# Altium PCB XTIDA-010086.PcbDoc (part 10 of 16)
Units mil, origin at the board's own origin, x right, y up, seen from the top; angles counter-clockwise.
Board outline 14763.78 x 8267.72 mil, 6 copper layers (Top Layer, GND Layer, Signal Layer 1, Signal Layer 2, Power Layer, Bottom Layer), stack 62 mil thick; 1933 components, 1002 nets, 4886 pads, 6482 vias.
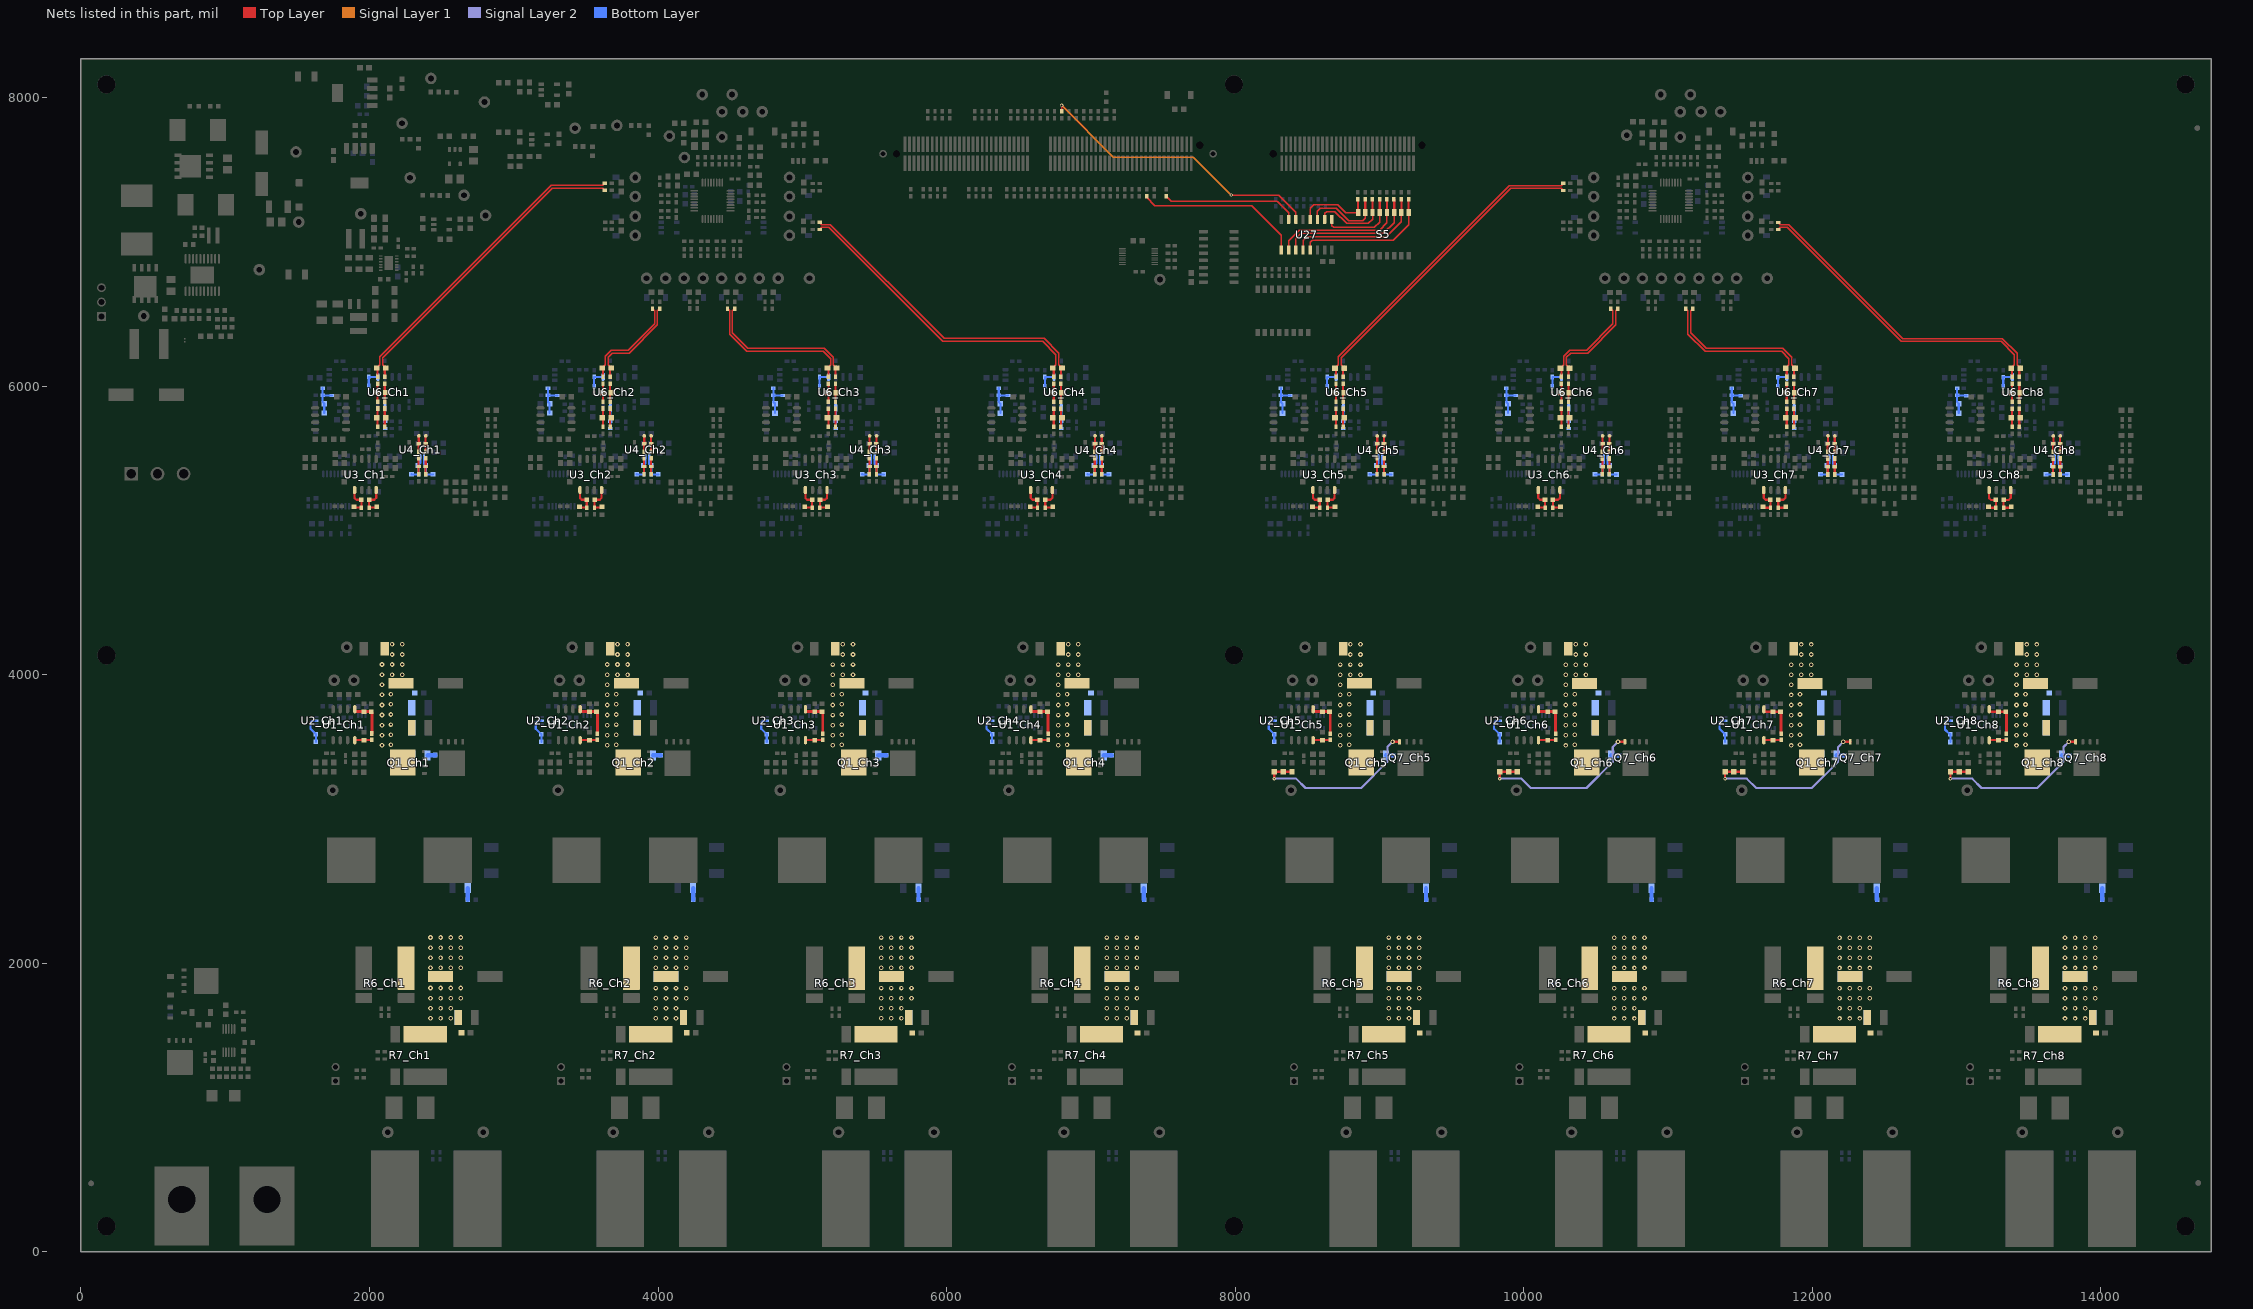
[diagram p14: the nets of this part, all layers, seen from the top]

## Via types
v1: diameter 32, hole 16, Top Layer to Bottom Layer, tented both sides, 4685 vias
v2: diameter 24, hole 12, Top Layer to Bottom Layer, tented both sides, 1013 vias
v3: diameter 32, hole 16, Top Layer to Bottom Layer, 728 vias
v4: diameter 19.68, hole 7.87, Top Layer to Bottom Layer, 40 vias
v5: diameter 214.57, hole 140, Top Layer to Bottom Layer, 16 vias

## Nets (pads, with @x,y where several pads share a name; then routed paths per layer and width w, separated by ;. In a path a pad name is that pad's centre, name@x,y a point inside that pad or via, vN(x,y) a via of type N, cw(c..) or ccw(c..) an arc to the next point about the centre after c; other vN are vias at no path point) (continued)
LDrive_Ch5: Q7_Ch5.4 R21_Ch5.1 R24_Ch5.2 R25_Ch5.2 | length 1257.7
  Top Layer w15: v2(8271.06,3279.33) R24_Ch5.2@8271.06,3327.28 R25_Ch5.2@8332.53,3327.28 R21_Ch5.1@8394.06,3327.28 ; v1(9090.75,3534.76) Q7_Ch5.4@9138.7,3534.76
  Signal Layer 2 w15: v2(8271.06,3279.33) 8422.06,3279.33 8486.7,3214.69 8872.7,3214.69 9054.7,3396.69 9054.7,3498.72 v1(9090.75,3534.76)
LDrive_Ch6: Q7_Ch6.4 R21_Ch6.1 R24_Ch6.2 R25_Ch6.2 | length 1257.7
  Top Layer w15: v2(9833.06,3279.25) R24_Ch6.2@9833.06,3327.2 R25_Ch6.2@9894.53,3327.2 R21_Ch6.1@9956.06,3327.2 ; v1(10652.75,3534.69) Q7_Ch6.4@10700.7,3534.69
  Signal Layer 2 w15: v2(9833.06,3279.25) 9984.06,3279.25 10048.7,3214.61 10434.7,3214.61 10616.7,3396.61 10616.7,3498.64 v1(10652.75,3534.69)
LDrive_Ch7: Q7_Ch7.4 R21_Ch7.1 R24_Ch7.2 R25_Ch7.2 | length 1257.7
  Top Layer w15: v2(11395.06,3279.17) R24_Ch7.2@11395.06,3327.12 R25_Ch7.2@11456.53,3327.12 R21_Ch7.1@11518.06,3327.12 ; v1(12214.75,3534.61) Q7_Ch7.4@12262.7,3534.61
  Signal Layer 2 w15: v2(11395.06,3279.17) 11546.06,3279.17 11610.7,3214.53 11996.7,3214.53 12178.7,3396.53 12178.7,3498.56 v1(12214.75,3534.61)
LDrive_Ch8: Q7_Ch8.4 R21_Ch8.1 R24_Ch8.2 R25_Ch8.2 | length 1257.7
  Top Layer w15: v2(12957.06,3279.09) R24_Ch8.2@12957.06,3327.05 R25_Ch8.2@13018.53,3327.05 R21_Ch8.1@13080.06,3327.05 ; v1(13776.75,3534.53) Q7_Ch8.4@13824.7,3534.53
  Signal Layer 2 w15: v2(12957.06,3279.09) 13108.06,3279.09 13172.7,3214.45 13558.7,3214.45 13740.7,3396.45 13740.7,3498.48 v1(13776.75,3534.53)
LTV_-2.5V_Ch1: C55_Ch1.2 R76_Ch1.1 R78_Ch1.2 R79_Ch1.2 R219_Ch1.2 | length 240.8
  Bottom Layer w15: R219_Ch1.2@1675.38,5985 1675.62,5984.76 R79_Ch1.2@1675.62,5935.7 ; R78_Ch1.2@1686.71,5813.03 C55_Ch1.2@1686.71,5878.7 1675.62,5889.79 R79_Ch1.2@1675.62,5935.7 ; R76_Ch1.1@1739.38,5934.7 1738.38,5935.7 R79_Ch1.2@1675.62,5935.7
LTV_-2.5V_Ch2: C55_Ch2.2 R76_Ch2.1 R78_Ch2.2 R79_Ch2.2 R219_Ch2.2 | length 240.5
  Bottom Layer w15: R219_Ch2.2@3237.62,5984.68 R79_Ch2.2@3237.62,5935.62 ; R78_Ch2.2@3248.71,5812.95 C55_Ch2.2@3248.71,5878.62 3237.62,5889.71 R79_Ch2.2@3237.62,5935.62 ; R76_Ch2.1@3301.38,5934.62 3300.38,5935.62 R79_Ch2.2@3237.62,5935.62
LTV_-2.5V_Ch3: C55_Ch3.2 R76_Ch3.1 R78_Ch3.2 R79_Ch3.2 R219_Ch3.2 | length 240.5
  Bottom Layer w15: R219_Ch3.2@4799.62,5984.6 R79_Ch3.2@4799.62,5935.54 ; R78_Ch3.2@4810.71,5812.87 C55_Ch3.2@4810.71,5878.54 4799.62,5889.63 R79_Ch3.2@4799.62,5935.54 ; R76_Ch3.1@4863.38,5934.54 4862.38,5935.54 R79_Ch3.2@4799.62,5935.54
LTV_-2.5V_Ch4: C55_Ch4.2 R76_Ch4.1 R78_Ch4.2 R79_Ch4.2 R219_Ch4.2 | length 240.5
  Bottom Layer w15: R219_Ch4.2@6361.62,5984.52 R79_Ch4.2@6361.62,5935.46 ; R78_Ch4.2@6372.71,5812.79 C55_Ch4.2@6372.71,5878.46 6361.62,5889.55 R79_Ch4.2@6361.62,5935.46 ; R76_Ch4.1@6425.38,5934.46 6424.38,5935.46 R79_Ch4.2@6361.62,5935.46
LTV_-2.5V_Ch5: C55_Ch5.2 R76_Ch5.1 R78_Ch5.2 R79_Ch5.2 R219_Ch5.2 | length 240.5
  Bottom Layer w15: R219_Ch5.2@8317.32,5984.44 R79_Ch5.2@8317.32,5935.39 ; R78_Ch5.2@8328.41,5812.71 C55_Ch5.2@8328.41,5878.39 8317.32,5889.47 R79_Ch5.2@8317.32,5935.39 ; R76_Ch5.1@8381.08,5934.39 8380.08,5935.39 R79_Ch5.2@8317.32,5935.39
LTV_-2.5V_Ch6: C55_Ch6.2 R76_Ch6.1 R78_Ch6.2 R79_Ch6.2 R219_Ch6.2 | length 240.5
  Bottom Layer w15: R219_Ch6.2@9879.32,5984.36 R79_Ch6.2@9879.32,5935.31 ; R78_Ch6.2@9890.41,5812.63 C55_Ch6.2@9890.41,5878.31 9879.32,5889.39 R79_Ch6.2@9879.32,5935.31 ; R76_Ch6.1@9943.08,5934.31 9942.08,5935.31 R79_Ch6.2@9879.32,5935.31
LTV_-2.5V_Ch7: C55_Ch7.2 R76_Ch7.1 R78_Ch7.2 R79_Ch7.2 R219_Ch7.2 | length 240.5
  Bottom Layer w15: R219_Ch7.2@11441.32,5984.28 R79_Ch7.2@11441.32,5935.23 ; R78_Ch7.2@11452.41,5812.55 C55_Ch7.2@11452.41,5878.23 11441.32,5889.32 R79_Ch7.2@11441.32,5935.23 ; R76_Ch7.1@11505.08,5934.23 11504.08,5935.23 R79_Ch7.2@11441.32,5935.23
LTV_-2.5V_Ch8: C55_Ch8.2 R76_Ch8.1 R78_Ch8.2 R79_Ch8.2 R219_Ch8.2 | length 240.5
  Bottom Layer w15: R219_Ch8.2@13003.32,5984.2 R79_Ch8.2@13003.32,5935.15 ; R78_Ch8.2@13014.41,5812.48 C55_Ch8.2@13014.41,5878.15 13003.32,5889.24 R79_Ch8.2@13003.32,5935.15 ; R76_Ch8.1@13067.08,5934.15 13066.08,5935.15 R79_Ch8.2@13003.32,5935.15
MODE_A: R297.1 U27.9 | length 1152.3
  Top Layer w10: R297.1@7388,7316.38 7388,7307 7444,7251 8114,7251 8320.2,7044.8 U27.9@8320.2,6942.67
MODE_B: R296.1 U27.7 | length 943.1
  Top Layer w10: R296.1@7521,7316.38 7557.38,7280 8291.78,7280 8370.2,7201.58 U27.7@8370.2,7155.27
MODE_C: R274.1 U27.6 | length 2021.4
  Top Layer w10: R274.1@6797,7903.54 v2(6797,7945) ; v2(7972,7324) 8302,7324 8420.2,7205.8 U27.6@8420.2,7155.27
  Signal Layer 1 w10: v2(6797,7945) 7156,7586 7710,7586 v2(7972,7324)
MODE_CH1: R234.2 S5.4 U27.10 | length 962.7
  Top Layer w10: U27.10@8369.78,6942.25 U27.10@8370.2,6942.67 8370.2,7007.97 8442.78,7080.54 9001.78,7080.54 9051.86,7130.62 S5.4@9051.86,7202.54
  Top Layer w15: S5.4@9051.86,7202.54 R234.2@9051.86,7294.92
MODE_CH2: R233.2 S5.3 U27.11 | length 970.3
  Top Layer w10: U27.11@8420.2,6942.67 8419.78,6942.25 8419.78,7021.54 8456.2,7057.97 9027.2,7057.97 9101.86,7132.62 S5.3@9101.86,7202.54
  Top Layer w15: S5.3@9101.86,7202.54 R233.2@9101.86,7294.92
MODE_CH3: R232.2 S5.2 U27.12 | length 959
  Top Layer w10: U27.12@8471.08,6941.79 U27.12@8470.2,6942.67 8470.2,7008.97 8496.2,7034.97 9047.2,7034.97 9151.86,7139.62 S5.2@9151.86,7202.54
  Top Layer w15: R232.2@9150.86,7294.92 9151.86,7293.92 S5.2@9151.86,7202.54
MODE_CH4: R231.2 S5.1 U27.13 | length 964.4
  Top Layer w10: U27.13@8520.2,6942.67 8519.78,6942.25 8519.78,6996.54 8535.2,7011.97 9096.2,7011.97 9201.86,7117.62 S5.1@9201.86,7202.54
  Top Layer w15: S5.1@9201.86,7202.54 R231.2@9201.86,7294.92
MODE_CH5: R235.2 S5.5 U27.1 | length 554.8
  Top Layer w10: U27.1@8670.2,7155.27 8670.2,7110.97 8682.2,7098.97 8964.2,7098.97 9001.86,7136.62 S5.5@9001.86,7202.54
  Top Layer w15: S5.5@9001.86,7202.54 R235.2@9001.86,7294.92
MODE_CH6: R236.2 S5.6 U27.2 | length 560.9
  Top Layer w10: U27.2@8620.2,7155.27 8620.2,7195.97 8633.2,7208.97 8691.2,7208.97 8772.2,7127.97 8922.2,7127.97 8951.86,7157.62 S5.6@8951.86,7202.54
  Top Layer w15: S5.6@8951.86,7202.54 R236.2@8951.86,7294.92
MODE_CH7: R237.2 S5.7 U27.3 | length 570.5
  Top Layer w10: U27.3@8570.2,7155.27 8570.2,7212.97 8588.2,7230.97 8701.2,7230.97 8786.2,7145.97 8883.99,7145.97 8901.86,7163.84 S5.7@8901.86,7202.54
  Top Layer w15: S5.7@8901.86,7202.54 R237.2@8901.86,7294.92
MODE_CH8: R238.2 S5.8 U27.4 | length 532.8
  Top Layer w10: U27.4@8520.2,7155.27 8520.2,7231.97 8544.2,7255.97 8712.2,7255.97 8765.63,7202.54 S5.8@8851.86,7202.54
  Top Layer w15: S5.8@8851.86,7202.54 R238.2@8851.86,7294.92
NetC1_Ch1_1: C1_Ch1.1 D1_Ch1.1 U1_Ch1.8 | length 120.2
  Top Layer w15: U1_Ch1.8@1898.37,3545.79 1899.33,3546.75 C1_Ch1.1@1962.33,3546.75 2015.49,3546.75 D1_Ch1.1@2017.39,3548.65
NetC1_Ch2_1: C1_Ch2.1 D1_Ch2.1 U1_Ch2.8 | length 120.2
  Top Layer w15: U1_Ch2.8@3460.37,3545.71 3461.33,3546.67 C1_Ch2.1@3524.33,3546.67 3577.49,3546.67 D1_Ch2.1@3579.39,3548.58
NetC1_Ch3_1: C1_Ch3.1 D1_Ch3.1 U1_Ch3.8 | length 120.2
  Top Layer w15: U1_Ch3.8@5022.37,3545.63 5023.33,3546.59 C1_Ch3.1@5086.33,3546.59 5139.49,3546.59 D1_Ch3.1@5141.39,3548.5
NetC1_Ch4_1: C1_Ch4.1 D1_Ch4.1 U1_Ch4.8 | length 120.2
  Top Layer w15: U1_Ch4.8@6584.37,3545.55 6585.33,3546.51 C1_Ch4.1@6648.33,3546.51 6701.49,3546.51 D1_Ch4.1@6703.39,3548.42
NetC1_Ch5_1: C1_Ch5.1 D1_Ch5.1 U1_Ch5.8 | length 120.2
  Top Layer w15: U1_Ch5.8@8540.07,3545.47 8541.03,3546.43 C1_Ch5.1@8604.03,3546.43 8657.19,3546.43 D1_Ch5.1@8659.09,3548.34
NetC1_Ch6_1: C1_Ch6.1 D1_Ch6.1 U1_Ch6.8 | length 120.2
  Top Layer w15: U1_Ch6.8@10102.07,3545.39 10103.03,3546.35 C1_Ch6.1@10166.03,3546.35 10219.19,3546.35 D1_Ch6.1@10221.09,3548.26
NetC1_Ch7_1: C1_Ch7.1 D1_Ch7.1 U1_Ch7.8 | length 120.2
  Top Layer w15: U1_Ch7.8@11664.07,3545.31 11665.03,3546.28 C1_Ch7.1@11728.03,3546.28 11781.19,3546.28 D1_Ch7.1@11783.09,3548.18
NetC1_Ch8_1: C1_Ch8.1 D1_Ch8.1 U1_Ch8.8 | length 120.2
  Top Layer w15: U1_Ch8.8@13226.07,3545.23 13227.03,3546.2 C1_Ch8.1@13290.03,3546.2 13343.19,3546.2 D1_Ch8.1@13345.09,3548.1
NetC2_Ch1_2: C2_Ch1.2 R4_Ch1.2 | length 54.7
  Bottom Layer w30: R4_Ch1.2@2403.15,3441 2456.44,3441 C2_Ch1.2@2457.44,3442
NetC2_Ch2_2: C2_Ch2.2 R4_Ch2.2 | length 54.7
  Bottom Layer w30: R4_Ch2.2@3965.15,3440.92 4018.44,3440.92 C2_Ch2.2@4019.44,3441.92
NetC2_Ch3_2: C2_Ch3.2 R4_Ch3.2 | length 54.7
  Bottom Layer w30: R4_Ch3.2@5527.15,3440.84 5580.44,3440.84 C2_Ch3.2@5581.44,3441.84
NetC2_Ch4_2: C2_Ch4.2 R4_Ch4.2 | length 54.7
  Bottom Layer w30: R4_Ch4.2@7089.15,3440.76 7142.44,3440.76 C2_Ch4.2@7143.44,3441.76
NetC2_Ch5_2: C2_Ch5.2 R4_Ch5.2 | length 54.7
  Bottom Layer w30: R4_Ch5.2@9044.85,3440.69 9098.14,3440.69 C2_Ch5.2@9099.14,3441.69
NetC2_Ch6_2: C2_Ch6.2 R4_Ch6.2 | length 54.7
  Bottom Layer w30: R4_Ch6.2@10606.85,3440.61 10660.14,3440.61 C2_Ch6.2@10661.14,3441.61
NetC2_Ch7_2: C2_Ch7.2 R4_Ch7.2 | length 54.7
  Bottom Layer w30: R4_Ch7.2@12168.85,3440.53 12222.14,3440.53 C2_Ch7.2@12223.14,3441.53
NetC2_Ch8_2: C2_Ch8.2 R4_Ch8.2 | length 54.7
  Bottom Layer w30: R4_Ch8.2@13730.85,3440.45 13784.14,3440.45 C2_Ch8.2@13785.14,3441.45
NetC3_Ch1_1: C3_Ch1.1 C4_Ch1.1 C5_Ch1.1 C6_Ch1.1 C7_Ch1.1 L1_Ch1.2 Q1_Ch1.5 Q1_Ch1.6 Q1_Ch1.7 Q1_Ch1.8 Q1_Ch1.9@2231.39,3391 R4_Ch1.1
  other v1: 2087,3510 2149,3514 2087,3580 2149,3584 2087,3650 2149,3654 2087,3720 2149,3724 2087,3790 2149,3794 2087,3860 2149,3864 2087,3930 2087,4000 2157,4000 2227,4000 2087,4070 2157,4070 2227,4070 2157,4140 2227,4140 2157,4210 2227,4210
NetC3_Ch2_1: C3_Ch2.1 C4_Ch2.1 C5_Ch2.1 C6_Ch2.1 C7_Ch2.1 L1_Ch2.2 Q1_Ch2.5 Q1_Ch2.6 Q1_Ch2.7 Q1_Ch2.8 Q1_Ch2.9@3793.39,3390.92 R4_Ch2.1
  other v1: 3649,3509.92 3711,3513.92 3649,3579.92 3711,3583.92 3649,3649.92 3711,3653.92 3649,3719.92 3711,3723.92 3649,3789.92 3711,3793.92 3649,3859.92 3711,3863.92 3649,3929.92 3649,3999.92 3719,3999.92 3789,3999.92 3649,4069.92 3719,4069.92 3789,4069.92 3719,4139.92 3789,4139.92 3719,4209.92 3789,4209.92
NetC3_Ch3_1: C3_Ch3.1 C4_Ch3.1 C5_Ch3.1 C6_Ch3.1 C7_Ch3.1 L1_Ch3.2 Q1_Ch3.5 Q1_Ch3.6 Q1_Ch3.7 Q1_Ch3.8 Q1_Ch3.9@5355.39,3390.84 R4_Ch3.1
  other v1: 5211,3509.84 5273,3513.84 5211,3579.84 5273,3583.84 5211,3649.84 5273,3653.84 5211,3719.84 5273,3723.84 5211,3789.84 5273,3793.84 5211,3859.84 5273,3863.84 5211,3929.84 5211,3999.84 5281,3999.84 5351,3999.84 5211,4069.84 5281,4069.84 5351,4069.84 5281,4139.84 5351,4139.84 5281,4209.84 5351,4209.84
NetC3_Ch4_1: C3_Ch4.1 C4_Ch4.1 C5_Ch4.1 C6_Ch4.1 C7_Ch4.1 L1_Ch4.2 Q1_Ch4.5 Q1_Ch4.6 Q1_Ch4.7 Q1_Ch4.8 Q1_Ch4.9@6917.39,3390.76 R4_Ch4.1
  other v1: 6773,3509.76 6835,3513.76 6773,3579.76 6835,3583.76 6773,3649.76 6835,3653.76 6773,3719.76 6835,3723.76 6773,3789.76 6835,3793.76 6773,3859.76 6835,3863.76 6773,3929.76 6773,3999.76 6843,3999.76 6913,3999.76 6773,4069.76 6843,4069.76 6913,4069.76 6843,4139.76 6913,4139.76 6843,4209.76 6913,4209.76
NetC3_Ch5_1: C3_Ch5.1 C4_Ch5.1 C5_Ch5.1 C6_Ch5.1 C7_Ch5.1 L1_Ch5.2 Q1_Ch5.5 Q1_Ch5.6 Q1_Ch5.7 Q1_Ch5.8 Q1_Ch5.9@8873.09,3390.69 R4_Ch5.1
  other v1: 8728.7,3509.69 8790.7,3513.69 8728.7,3579.69 8790.7,3583.69 8728.7,3649.69 8790.7,3653.69 8728.7,3719.69 8790.7,3723.69 8728.7,3789.69 8790.7,3793.69 8728.7,3859.69 8790.7,3863.69 8728.7,3929.69 8728.7,3999.69 8798.7,3999.69 8868.7,3999.69 8728.7,4069.69 8798.7,4069.69 8868.7,4069.69 8798.7,4139.69 8868.7,4139.69 8798.7,4209.69 8868.7,4209.69
NetC3_Ch6_1: C3_Ch6.1 C4_Ch6.1 C5_Ch6.1 C6_Ch6.1 C7_Ch6.1 L1_Ch6.2 Q1_Ch6.5 Q1_Ch6.6 Q1_Ch6.7 Q1_Ch6.8 Q1_Ch6.9@10435.09,3390.61 R4_Ch6.1
  other v1: 10290.7,3509.61 10352.7,3513.61 10290.7,3579.61 10352.7,3583.61 10290.7,3649.61 10352.7,3653.61 10290.7,3719.61 10352.7,3723.61 10290.7,3789.61 10352.7,3793.61 10290.7,3859.61 10352.7,3863.61 10290.7,3929.61 10290.7,3999.61 10360.7,3999.61 10430.7,3999.61 10290.7,4069.61 10360.7,4069.61 10430.7,4069.61 10360.7,4139.61 10430.7,4139.61 10360.7,4209.61 10430.7,4209.61
NetC3_Ch7_1: C3_Ch7.1 C4_Ch7.1 C5_Ch7.1 C6_Ch7.1 C7_Ch7.1 L1_Ch7.2 Q1_Ch7.5 Q1_Ch7.6 Q1_Ch7.7 Q1_Ch7.8 Q1_Ch7.9@11997.09,3390.53 R4_Ch7.1
  other v1: 11852.7,3509.53 11914.7,3513.53 11852.7,3579.53 11914.7,3583.53 11852.7,3649.53 11914.7,3653.53 11852.7,3719.53 11914.7,3723.53 11852.7,3789.53 11914.7,3793.53 11852.7,3859.53 11914.7,3863.53 11852.7,3929.53 11852.7,3999.53 11922.7,3999.53 11992.7,3999.53 11852.7,4069.53 11922.7,4069.53 11992.7,4069.53 11922.7,4139.53 11992.7,4139.53 11922.7,4209.53 11992.7,4209.53
NetC3_Ch8_1: C3_Ch8.1 C4_Ch8.1 C5_Ch8.1 C6_Ch8.1 C7_Ch8.1 L1_Ch8.2 Q1_Ch8.5 Q1_Ch8.6 Q1_Ch8.7 Q1_Ch8.8 Q1_Ch8.9@13559.09,3390.45 R4_Ch8.1
  other v1: 13414.7,3509.45 13476.7,3513.45 13414.7,3579.45 13476.7,3583.45 13414.7,3649.45 13476.7,3653.45 13414.7,3719.45 13476.7,3723.45 13414.7,3789.45 13476.7,3793.45 13414.7,3859.45 13476.7,3863.45 13414.7,3929.45 13414.7,3999.45 13484.7,3999.45 13554.7,3999.45 13414.7,4069.45 13484.7,4069.45 13554.7,4069.45 13484.7,4139.45 13554.7,4139.45 13484.7,4209.45 13554.7,4209.45
NetC8_Ch1_2: C8_Ch1.2 D1_Ch1.2 R8_Ch1.1 U1_Ch1.1 | length 283.2
  Top Layer w20: U1_Ch1.1@1898.37,3760.35 1898.37,3745.86 1900.53,3743.7 C8_Ch1.2@1962.33,3743.7 R8_Ch1.1@2012.39,3743.7 2017.39,3738.7 D1_Ch1.2@2017.39,3591.96
NetC8_Ch2_2: C8_Ch2.2 D1_Ch2.2 R8_Ch2.1 U1_Ch2.1 | length 283.2
  Top Layer w20: U1_Ch2.1@3460.37,3760.27 3460.37,3745.78 3462.53,3743.62 C8_Ch2.2@3524.33,3743.62 R8_Ch2.1@3574.39,3743.62 3579.39,3738.62 D1_Ch2.2@3579.39,3591.88
NetC8_Ch3_2: C8_Ch3.2 D1_Ch3.2 R8_Ch3.1 U1_Ch3.1 | length 283.2
  Top Layer w20: U1_Ch3.1@5022.37,3760.19 5022.37,3745.7 5024.53,3743.54 C8_Ch3.2@5086.33,3743.54 R8_Ch3.1@5136.39,3743.54 5141.39,3738.54 D1_Ch3.2@5141.39,3591.8
NetC8_Ch4_2: C8_Ch4.2 D1_Ch4.2 R8_Ch4.1 U1_Ch4.1 | length 283.2
  Top Layer w20: U1_Ch4.1@6584.37,3760.12 6584.37,3745.62 6586.53,3743.46 C8_Ch4.2@6648.33,3743.46 R8_Ch4.1@6698.39,3743.46 6703.39,3738.46 D1_Ch4.2@6703.39,3591.73
NetC8_Ch5_2: C8_Ch5.2 D1_Ch5.2 R8_Ch5.1 U1_Ch5.1 | length 283.2
  Top Layer w20: U1_Ch5.1@8540.07,3760.04 8540.07,3745.54 8542.23,3743.38 C8_Ch5.2@8604.03,3743.38 R8_Ch5.1@8654.09,3743.38 8659.09,3738.38 D1_Ch5.2@8659.09,3591.65
NetC8_Ch6_2: C8_Ch6.2 D1_Ch6.2 R8_Ch6.1 U1_Ch6.1 | length 283.2
  Top Layer w20: U1_Ch6.1@10102.07,3759.96 10102.07,3745.46 10104.23,3743.31 C8_Ch6.2@10166.03,3743.31 R8_Ch6.1@10216.09,3743.31 10221.09,3738.31 D1_Ch6.2@10221.09,3591.57
NetC8_Ch7_2: C8_Ch7.2 D1_Ch7.2 R8_Ch7.1 U1_Ch7.1 | length 283.2
  Top Layer w20: U1_Ch7.1@11664.07,3759.88 11664.07,3745.38 11666.23,3743.23 C8_Ch7.2@11728.03,3743.23 R8_Ch7.1@11778.09,3743.23 11783.09,3738.23 D1_Ch7.2@11783.09,3591.49
NetC8_Ch8_2: C8_Ch8.2 D1_Ch8.2 R8_Ch8.1 U1_Ch8.1 | length 283.2
  Top Layer w20: U1_Ch8.1@13226.07,3759.8 13226.07,3745.31 13228.23,3743.15 C8_Ch8.2@13290.03,3743.15 R8_Ch8.1@13340.09,3743.15 13345.09,3738.15 D1_Ch8.2@13345.09,3591.41
NetC9_Ch1_1: C9_Ch1.1 C10_Ch1.1 C11_Ch1.1 C12_Ch1.1 C13_Ch1.1 R6_Ch1.1 R7_Ch1.2
  other v1: 2423,1618 2493,1618 2563,1618 2423,1688 2493,1688 2563,1688 2423,1758 2493,1758 2563,1758 2633,1758 2423,1828 2493,1828 2563,1828 2633,1828 2423,1968 2493,1968 2563,1968 2633,1968 2423,2038 2493,2038 2563,2038 2633,2038 2423,2108 2493,2108 2563,2108 2633,2108 2423,2178 2493,2178 2563,2178 2633,2178
NetC9_Ch2_1: C9_Ch2.1 C10_Ch2.1 C11_Ch2.1 C12_Ch2.1 C13_Ch2.1 R6_Ch2.1 R7_Ch2.2
  other v1: 3985,1617.92 4055,1617.92 4125,1617.92 3985,1687.92 4055,1687.92 4125,1687.92 3985,1757.92 4055,1757.92 4125,1757.92 4195,1757.92 3985,1827.92 4055,1827.92 4125,1827.92 4195,1827.92 3985,1967.92 4055,1967.92 4125,1967.92 4195,1967.92 3985,2037.92 4055,2037.92 4125,2037.92 4195,2037.92 3985,2107.92 4055,2107.92 4125,2107.92 4195,2107.92 3985,2177.92 4055,2177.92 4125,2177.92 4195,2177.92
NetC9_Ch3_1: C9_Ch3.1 C10_Ch3.1 C11_Ch3.1 C12_Ch3.1 C13_Ch3.1 R6_Ch3.1 R7_Ch3.2
  other v1: 5547,1617.84 5617,1617.84 5687,1617.84 5547,1687.84 5617,1687.84 5687,1687.84 5547,1757.84 5617,1757.84 5687,1757.84 5757,1757.84 5547,1827.84 5617,1827.84 5687,1827.84 5757,1827.84 5547,1967.84 5617,1967.84 5687,1967.84 5757,1967.84 5547,2037.84 5617,2037.84 5687,2037.84 5757,2037.84 5547,2107.84 5617,2107.84 5687,2107.84 5757,2107.84 5547,2177.84 5617,2177.84 5687,2177.84 5757,2177.84
NetC9_Ch4_1: C9_Ch4.1 C10_Ch4.1 C11_Ch4.1 C12_Ch4.1 C13_Ch4.1 R6_Ch4.1 R7_Ch4.2
  other v1: 7109,1617.76 7179,1617.76 7249,1617.76 7109,1687.76 7179,1687.76 7249,1687.76 7109,1757.76 7179,1757.76 7249,1757.76 7319,1757.76 7109,1827.76 7179,1827.76 7249,1827.76 7319,1827.76 7109,1967.76 7179,1967.76 7249,1967.76 7319,1967.76 7109,2037.76 7179,2037.76 7249,2037.76 7319,2037.76 7109,2107.76 7179,2107.76 7249,2107.76 7319,2107.76 7109,2177.76 7179,2177.76 7249,2177.76 7319,2177.76
NetC9_Ch5_1: C9_Ch5.1 C10_Ch5.1 C11_Ch5.1 C12_Ch5.1 C13_Ch5.1 R6_Ch5.1 R7_Ch5.2
  other v1: 9064.7,1617.69 9134.7,1617.69 9204.7,1617.69 9064.7,1687.69 9134.7,1687.69 9204.7,1687.69 9064.7,1757.69 9134.7,1757.69 9204.7,1757.69 9274.7,1757.69 9064.7,1827.69 9134.7,1827.69 9204.7,1827.69 9274.7,1827.69 9064.7,1967.69 9134.7,1967.69 9204.7,1967.69 9274.7,1967.69 9064.7,2037.69 9134.7,2037.69 9204.7,2037.69 9274.7,2037.69 9064.7,2107.69 9134.7,2107.69 9204.7,2107.69 9274.7,2107.69 9064.7,2177.69 9134.7,2177.69 9204.7,2177.69 9274.7,2177.69
NetC9_Ch6_1: C9_Ch6.1 C10_Ch6.1 C11_Ch6.1 C12_Ch6.1 C13_Ch6.1 R6_Ch6.1 R7_Ch6.2
  other v1: 10626.7,1617.61 10696.7,1617.61 10766.7,1617.61 10626.7,1687.61 10696.7,1687.61 10766.7,1687.61 10626.7,1757.61 10696.7,1757.61 10766.7,1757.61 10836.7,1757.61 10626.7,1827.61 10696.7,1827.61 10766.7,1827.61 10836.7,1827.61 10626.7,1967.61 10696.7,1967.61 10766.7,1967.61 10836.7,1967.61 10626.7,2037.61 10696.7,2037.61 10766.7,2037.61 10836.7,2037.61 10626.7,2107.61 10696.7,2107.61 10766.7,2107.61 10836.7,2107.61 10626.7,2177.61 10696.7,2177.61 10766.7,2177.61 10836.7,2177.61
NetC9_Ch7_1: C9_Ch7.1 C10_Ch7.1 C11_Ch7.1 C12_Ch7.1 C13_Ch7.1 R6_Ch7.1 R7_Ch7.2
  other v1: 12188.7,1617.53 12258.7,1617.53 12328.7,1617.53 12188.7,1687.53 12258.7,1687.53 12328.7,1687.53 12188.7,1757.53 12258.7,1757.53 12328.7,1757.53 12398.7,1757.53 12188.7,1827.53 12258.7,1827.53 12328.7,1827.53 12398.7,1827.53 12188.7,1967.53 12258.7,1967.53 12328.7,1967.53 12398.7,1967.53 12188.7,2037.53 12258.7,2037.53 12328.7,2037.53 12398.7,2037.53 12188.7,2107.53 12258.7,2107.53 12328.7,2107.53 12398.7,2107.53 12188.7,2177.53 12258.7,2177.53 12328.7,2177.53 12398.7,2177.53
NetC9_Ch8_1: C9_Ch8.1 C10_Ch8.1 C11_Ch8.1 C12_Ch8.1 C13_Ch8.1 R6_Ch8.1 R7_Ch8.2
  other v1: 13750.7,1617.45 13820.7,1617.45 13890.7,1617.45 13750.7,1687.45 13820.7,1687.45 13890.7,1687.45 13750.7,1757.45 13820.7,1757.45 13890.7,1757.45 13960.7,1757.45 13750.7,1827.45 13820.7,1827.45 13890.7,1827.45 13960.7,1827.45 13750.7,1967.45 13820.7,1967.45 13890.7,1967.45 13960.7,1967.45 13750.7,2037.45 13820.7,2037.45 13890.7,2037.45 13960.7,2037.45 13750.7,2107.45 13820.7,2107.45 13890.7,2107.45 13960.7,2107.45 13750.7,2177.45 13820.7,2177.45 13890.7,2177.45 13960.7,2177.45
NetC14_Ch1_2: C14_Ch1.2 R172_Ch1.2 U2_Ch1.5 | length 194.4
  Bottom Layer w15: R172_Ch1.2@1629.44,3534.69 C14_Ch1.2@1629.44,3587 1591,3625.44 1591,3669.78 1602.22,3681 U2_Ch1.5@1629.71,3681
NetC14_Ch2_2: C14_Ch2.2 R172_Ch2.2 U2_Ch2.5 | length 194.4
  Bottom Layer w15: R172_Ch2.2@3191.44,3534.61 C14_Ch2.2@3191.44,3586.92 3153,3625.36 3153,3669.7 3164.22,3680.92 U2_Ch2.5@3191.71,3680.92
NetC14_Ch3_2: C14_Ch3.2 R172_Ch3.2 U2_Ch3.5 | length 218.1
  Bottom Layer w15: 4715,3649 4715,3625.28 ; R172_Ch3.2@4753.44,3534.53 C14_Ch3.2@4753.44,3586.84 4715,3625.28 ; U2_Ch3.5@4753.71,3680.84 4726.22,3680.84 4715,3669.62 4715,3625.28
NetC14_Ch4_2: C14_Ch4.2 R172_Ch4.2 U2_Ch4.5 | length 220.2
  Bottom Layer w15: 6277,3651 6277,3625.2 ; R172_Ch4.2@6315.44,3534.45 C14_Ch4.2@6315.44,3586.76 6277,3625.2 ; U2_Ch4.5@6315.71,3680.76 6288.22,3680.76 6277,3669.54 6277,3625.2
NetC14_Ch5_2: C14_Ch5.2 R172_Ch5.2 U2_Ch5.5 | length 194.4
  Bottom Layer w15: R172_Ch5.2@8271.14,3534.37 C14_Ch5.2@8271.14,3586.69 8232.7,3625.13 8232.7,3669.46 8243.92,3680.69 U2_Ch5.5@8271.41,3680.69
NetC14_Ch6_2: C14_Ch6.2 R172_Ch6.2 U2_Ch6.5 | length 209.3
  Bottom Layer w15: 9794.7,3640 9794.7,3625.05 ; R172_Ch6.2@9833.14,3534.29 C14_Ch6.2@9833.14,3586.61 9794.7,3625.05 ; U2_Ch6.5@9833.41,3680.61 9805.92,3680.61 9794.7,3669.38 9794.7,3625.05
NetC14_Ch7_2: C14_Ch7.2 R172_Ch7.2 U2_Ch7.5 | length 209.4
  Bottom Layer w15: 11356.7,3640 11356.7,3624.97 ; R172_Ch7.2@11395.14,3534.21 C14_Ch7.2@11395.14,3586.53 11356.7,3624.97 ; U2_Ch7.5@11395.41,3680.53 11367.92,3680.53 11356.7,3669.3 11356.7,3624.97
NetC14_Ch8_2: C14_Ch8.2 R172_Ch8.2 U2_Ch8.5 | length 219.4
  Bottom Layer w15: 12918.7,3624.89 12918.7,3669.23 12929.92,3680.45 U2_Ch8.5@12957.41,3680.45 ; 12918.7,3646.67 12918.7,3619.3 12951.55,3586.45 C14_Ch8.2@12957.14,3586.45 R172_Ch8.2@12957.14,3534.13
NetC15_Ch1_2: C15_Ch1.2 R9_Ch1.2 | length 80.5
  Bottom Layer w30: R9_Ch1.2@2681.15,2520 2681.15,2441.29 C15_Ch1.2@2682.44,2440
NetC15_Ch2_2: C15_Ch2.2 R9_Ch2.2 | length 80.5
  Bottom Layer w30: R9_Ch2.2@4243.15,2519.92 4243.15,2441.21 C15_Ch2.2@4244.44,2439.92
NetC15_Ch3_2: C15_Ch3.2 R9_Ch3.2 | length 80.5
  Bottom Layer w30: R9_Ch3.2@5805.15,2519.84 5805.15,2441.13 C15_Ch3.2@5806.44,2439.84
NetC15_Ch4_2: C15_Ch4.2 R9_Ch4.2 | length 80.5
  Bottom Layer w30: R9_Ch4.2@7367.15,2519.76 7367.15,2441.06 C15_Ch4.2@7368.44,2439.76
NetC15_Ch5_2: C15_Ch5.2 R9_Ch5.2 | length 80.5
  Bottom Layer w30: R9_Ch5.2@9322.85,2519.69 9322.85,2440.98 C15_Ch5.2@9324.14,2439.69
NetC15_Ch6_2: C15_Ch6.2 R9_Ch6.2 | length 80.5
  Bottom Layer w30: R9_Ch6.2@10884.85,2519.61 10884.85,2440.9 C15_Ch6.2@10886.14,2439.61
NetC15_Ch7_2: C15_Ch7.2 R9_Ch7.2 | length 80.5
  Bottom Layer w30: R9_Ch7.2@12446.85,2519.53 12446.85,2440.82 C15_Ch7.2@12448.14,2439.53
NetC15_Ch8_2: C15_Ch8.2 R9_Ch8.2 | length 80.5
  Bottom Layer w30: R9_Ch8.2@14008.85,2519.45 14008.85,2440.74 C15_Ch8.2@14010.14,2439.45
NetC16_Ch1_1: C16_Ch1.1 R22_Ch1.2 R23_Ch1.1 | length 111.1
  Top Layer w15: R22_Ch1.2@2390,5387.67 2389.62,5388.05 C16_Ch1.1@2389.62,5442.56 2390,5442.93 R23_Ch1.1@2390,5498.43
NetC16_Ch1_2: C16_Ch1.2 R26_Ch1.2 R27_Ch1.1 | length 110.8
  Top Layer w15: R26_Ch1.2@2341,5387.67 R27_Ch1.1@2341,5498.43
NetC16_Ch2_1: C16_Ch2.1 R22_Ch2.2 R23_Ch2.1 | length 111.1
  Top Layer w15: R22_Ch2.2@3952,5387.59 3951.62,5387.97 C16_Ch2.1@3951.62,5442.48 3952,5442.86 R23_Ch2.1@3952,5498.35
NetC16_Ch2_2: C16_Ch2.2 R26_Ch2.2 R27_Ch2.1 | length 110.8
  Top Layer w15: R26_Ch2.2@3903,5387.59 R27_Ch2.1@3903,5498.35
NetC16_Ch3_1: C16_Ch3.1 R22_Ch3.2 R23_Ch3.1 | length 111.1
  Top Layer w15: R22_Ch3.2@5514,5387.51 5513.62,5387.89 C16_Ch3.1@5513.62,5442.4 5514,5442.78 R23_Ch3.1@5514,5498.27
NetC16_Ch3_2: C16_Ch3.2 R26_Ch3.2 R27_Ch3.1 | length 110.8
  Top Layer w15: R26_Ch3.2@5465,5387.51 R27_Ch3.1@5465,5498.27
NetC16_Ch4_1: C16_Ch4.1 R22_Ch4.2 R23_Ch4.1 | length 111.1
  Top Layer w15: R22_Ch4.2@7076,5387.43 7075.62,5387.81 C16_Ch4.1@7075.62,5442.32 7076,5442.7 R23_Ch4.1@7076,5498.19
NetC16_Ch4_2: C16_Ch4.2 R26_Ch4.2 R27_Ch4.1 | length 110.8
  Top Layer w15: R26_Ch4.2@7027,5387.43 R27_Ch4.1@7027,5498.19
NetC16_Ch5_1: C16_Ch5.1 R22_Ch5.2 R23_Ch5.1 | length 111.1
  Top Layer w15: R22_Ch5.2@9031.7,5387.35 9031.32,5387.73 C16_Ch5.1@9031.32,5442.24 9031.7,5442.62 R23_Ch5.1@9031.7,5498.11
NetC16_Ch5_2: C16_Ch5.2 R26_Ch5.2 R27_Ch5.1 | length 110.8
  Top Layer w15: R26_Ch5.2@8982.7,5387.35 R27_Ch5.1@8982.7,5498.11
NetC16_Ch6_1: C16_Ch6.1 R22_Ch6.2 R23_Ch6.1 | length 111.1
  Top Layer w15: R22_Ch6.2@10593.7,5387.28 10593.32,5387.65 C16_Ch6.1@10593.32,5442.16 10593.7,5442.54 R23_Ch6.1@10593.7,5498.03
NetC16_Ch6_2: C16_Ch6.2 R26_Ch6.2 R27_Ch6.1 | length 110.8
  Top Layer w15: R26_Ch6.2@10544.7,5387.28 R27_Ch6.1@10544.7,5498.03
NetC16_Ch7_1: C16_Ch7.1 R22_Ch7.2 R23_Ch7.1 | length 111.1
  Top Layer w15: R22_Ch7.2@12155.7,5387.2 12155.32,5387.57 C16_Ch7.1@12155.32,5442.09 12155.7,5442.46 R23_Ch7.1@12155.7,5497.95
NetC16_Ch7_2: C16_Ch7.2 R26_Ch7.2 R27_Ch7.1 | length 110.8
  Top Layer w15: R26_Ch7.2@12106.7,5387.2 R27_Ch7.1@12106.7,5497.95
NetC16_Ch8_1: C16_Ch8.1 R22_Ch8.2 R23_Ch8.1 | length 111.1
  Top Layer w15: R22_Ch8.2@13717.7,5387.12 13717.32,5387.5 C16_Ch8.1@13717.32,5442.01 13717.7,5442.38 R23_Ch8.1@13717.7,5497.87
NetC16_Ch8_2: C16_Ch8.2 R26_Ch8.2 R27_Ch8.1 | length 110.8
  Top Layer w15: R26_Ch8.2@13668.7,5387.12 R27_Ch8.1@13668.7,5497.87
NetC17_Ch1_1: C17_Ch1.1 CS+1_Ch1.1 R23_Ch1.2 | length 109.9
  Top Layer w15: R23_Ch1.2@2390,5545.67 2389.62,5546.05 C17_Ch1.1@2389.62,5601.05 2389.62,5654.17 CS+1_Ch1.1@2390.5,5655.05
NetC17_Ch1_2: C17_Ch1.2 CS-1_Ch1.1 R27_Ch1.2 | length 110
  Top Layer w15: R27_Ch1.2@2341,5545.67 2341,5599.67 C17_Ch1.2@2342.38,5601.05 2342.38,5654.93 CS-1_Ch1.1@2342.5,5655.05
NetC17_Ch2_1: C17_Ch2.1 CS+1_Ch2.1 R23_Ch2.2 | length 109.9
  Top Layer w15: R23_Ch2.2@3952,5545.59 3951.62,5545.97 C17_Ch2.1@3951.62,5600.97 3951.62,5654.09 CS+1_Ch2.1@3952.5,5654.97
NetC17_Ch2_2: C17_Ch2.2 CS-1_Ch2.1 R27_Ch2.2 | length 110
  Top Layer w15: R27_Ch2.2@3903,5545.59 3903,5599.59 C17_Ch2.2@3904.38,5600.97 3904.38,5654.85 CS-1_Ch2.1@3904.5,5654.97
NetC17_Ch3_1: C17_Ch3.1 CS+1_Ch3.1 R23_Ch3.2 | length 109.9
  Top Layer w15: R23_Ch3.2@5514,5545.51 5513.62,5545.89 C17_Ch3.1@5513.62,5600.89 5513.62,5654.01 CS+1_Ch3.1@5514.5,5654.89
NetC17_Ch3_2: C17_Ch3.2 CS-1_Ch3.1 R27_Ch3.2 | length 110
  Top Layer w15: R27_Ch3.2@5465,5545.51 5465,5599.51 C17_Ch3.2@5466.38,5600.89 5466.38,5654.77 CS-1_Ch3.1@5466.5,5654.89
NetC17_Ch4_1: C17_Ch4.1 CS+1_Ch4.1 R23_Ch4.2 | length 109.9
  Top Layer w15: R23_Ch4.2@7076,5545.43 7075.62,5545.81 C17_Ch4.1@7075.62,5600.81 7075.62,5653.93 CS+1_Ch4.1@7076.5,5654.81
NetC17_Ch4_2: C17_Ch4.2 CS-1_Ch4.1 R27_Ch4.2 | length 110
  Top Layer w15: R27_Ch4.2@7027,5545.43 7027,5599.43 C17_Ch4.2@7028.38,5600.81 7028.38,5654.69 CS-1_Ch4.1@7028.5,5654.81
NetC17_Ch5_1: C17_Ch5.1 CS+1_Ch5.1 R23_Ch5.2 | length 109.9
  Top Layer w15: R23_Ch5.2@9031.7,5545.35 9031.32,5545.73 C17_Ch5.1@9031.32,5600.73 9031.32,5653.85 CS+1_Ch5.1@9032.2,5654.73
NetC17_Ch5_2: C17_Ch5.2 CS-1_Ch5.1 R27_Ch5.2 | length 110
  Top Layer w15: R27_Ch5.2@8982.7,5545.35 8982.7,5599.35 C17_Ch5.2@8984.08,5600.73 8984.08,5654.61 CS-1_Ch5.1@8984.2,5654.73
NetC17_Ch6_1: C17_Ch6.1 CS+1_Ch6.1 R23_Ch6.2 | length 109.9
  Top Layer w15: R23_Ch6.2@10593.7,5545.28 10593.32,5545.65 C17_Ch6.1@10593.32,5600.65 10593.32,5653.78 CS+1_Ch6.1@10594.2,5654.65
NetC17_Ch6_2: C17_Ch6.2 CS-1_Ch6.1 R27_Ch6.2 | length 110
  Top Layer w15: R27_Ch6.2@10544.7,5545.28 10544.7,5599.28 C17_Ch6.2@10546.08,5600.65 10546.08,5654.53 CS-1_Ch6.1@10546.2,5654.65
NetC17_Ch7_1: C17_Ch7.1 CS+1_Ch7.1 R23_Ch7.2 | length 109.9
  Top Layer w15: R23_Ch7.2@12155.7,5545.2 12155.32,5545.57 C17_Ch7.1@12155.32,5600.57 12155.32,5653.7 CS+1_Ch7.1@12156.2,5654.57
NetC17_Ch7_2: C17_Ch7.2 CS-1_Ch7.1 R27_Ch7.2 | length 110
  Top Layer w15: R27_Ch7.2@12106.7,5545.2 12106.7,5599.2 C17_Ch7.2@12108.08,5600.57 12108.08,5654.45 CS-1_Ch7.1@12108.2,5654.57
NetC17_Ch8_1: C17_Ch8.1 CS+1_Ch8.1 R23_Ch8.2 | length 109.9
  Top Layer w15: R23_Ch8.2@13717.7,5545.12 13717.7,5600.12 C17_Ch8.1@13717.32,5600.5 13717.32,5653.62 CS+1_Ch8.1@13718.2,5654.5
NetC17_Ch8_2: C17_Ch8.2 CS-1_Ch8.1 R27_Ch8.2 | length 110
  Top Layer w15: R27_Ch8.2@13668.7,5545.12 13668.7,5599.12 C17_Ch8.2@13670.08,5600.5 13670.08,5654.37 CS-1_Ch8.1@13670.2,5654.5
NetC19_Ch1_1: C19_Ch1.1 C22_Ch1.1 R28_Ch1.2 U3_Ch1.1 | length 214.4
  Top Layer w15: C22_Ch1.1@1893.2,5162.81 1898.34,5157.67 R28_Ch1.2@1944,5157.67 1944,5211.49 C19_Ch1.1@1943.44,5212.05 1909.44,5212.05 1897,5224.49 U3_Ch1.1@1897,5279.76
NetC19_Ch1_2: C19_Ch1.2 C21_Ch1.2 R29_Ch1.2 U3_Ch1.4 | length 217.6
  Top Layer w15: U3_Ch1.4@2047,5279.76 2047,5224.91 2034.13,5212.05 C19_Ch1.2@1998.56,5212.05 1998,5211.49 R29_Ch1.2@1998,5157.67 2045.07,5157.67 C21_Ch1.2@2050.2,5162.81
NetC19_Ch2_1: C19_Ch2.1 C22_Ch2.1 R28_Ch2.2 U3_Ch2.1 | length 214.4
  Top Layer w15: C22_Ch2.1@3455.2,5162.73 3460.34,5157.59 R28_Ch2.2@3506,5157.59 3506,5211.41 C19_Ch2.1@3505.44,5211.97 3471.44,5211.97 3459,5224.41 U3_Ch2.1@3459,5279.68
NetC19_Ch2_2: C19_Ch2.2 C21_Ch2.2 R29_Ch2.2 U3_Ch2.4 | length 217.6
  Top Layer w15: U3_Ch2.4@3609,5279.68 3609,5224.83 3596.13,5211.97 C19_Ch2.2@3560.56,5211.97 3560,5211.41 R29_Ch2.2@3560,5157.59 3607.07,5157.59 C21_Ch2.2@3612.2,5162.73
NetC19_Ch3_1: C19_Ch3.1 C22_Ch3.1 R28_Ch3.2 U3_Ch3.1 | length 214.4
  Top Layer w15: C22_Ch3.1@5017.2,5162.65 5022.34,5157.51 R28_Ch3.2@5068,5157.51 5068,5211.33 C19_Ch3.1@5067.44,5211.89 5033.44,5211.89 5021,5224.33 U3_Ch3.1@5021,5279.61
NetC19_Ch3_2: C19_Ch3.2 C21_Ch3.2 R29_Ch3.2 U3_Ch3.4 | length 217.6
  Top Layer w15: U3_Ch3.4@5171,5279.61 5171,5224.76 5158.13,5211.89 C19_Ch3.2@5122.56,5211.89 5122,5211.33 R29_Ch3.2@5122,5157.51 5169.07,5157.51 C21_Ch3.2@5174.2,5162.65
NetC19_Ch4_1: C19_Ch4.1 C22_Ch4.1 R28_Ch4.2 U3_Ch4.1 | length 214.4
  Top Layer w15: C22_Ch4.1@6579.2,5162.57 6584.34,5157.43 R28_Ch4.2@6630,5157.43 6630,5211.25 C19_Ch4.1@6629.44,5211.81 6595.44,5211.81 6583,5224.25 U3_Ch4.1@6583,5279.53
NetC19_Ch4_2: C19_Ch4.2 C21_Ch4.2 R29_Ch4.2 U3_Ch4.4 | length 217.6
  Top Layer w15: U3_Ch4.4@6733,5279.53 6733,5224.68 6720.13,5211.81 C19_Ch4.2@6684.56,5211.81 6684,5211.25 R29_Ch4.2@6684,5157.43 6731.07,5157.43 C21_Ch4.2@6736.2,5162.57
NetC19_Ch5_1: C19_Ch5.1 C22_Ch5.1 R28_Ch5.2 U3_Ch5.1 | length 214.4
  Top Layer w15: C22_Ch5.1@8534.91,5162.49 8540.04,5157.35 R28_Ch5.2@8585.7,5157.35 8585.7,5211.17 C19_Ch5.1@8585.14,5211.73 8551.14,5211.73 8538.7,5224.17 U3_Ch5.1@8538.7,5279.45
NetC19_Ch5_2: C19_Ch5.2 C21_Ch5.2 R29_Ch5.2 U3_Ch5.4 | length 217.6
  Top Layer w15: U3_Ch5.4@8688.7,5279.45 8688.7,5224.6 8675.83,5211.73 C19_Ch5.2@8640.26,5211.73 8639.7,5211.17 R29_Ch5.2@8639.7,5157.35 8686.77,5157.35 C21_Ch5.2@8691.91,5162.49
NetC19_Ch6_1: C19_Ch6.1 C22_Ch6.1 R28_Ch6.2 U3_Ch6.1 | length 214.4
  Top Layer w15: C22_Ch6.1@10096.91,5162.41 10102.04,5157.28 R28_Ch6.2@10147.7,5157.28 10147.7,5211.09 C19_Ch6.1@10147.14,5211.65 10113.14,5211.65 10100.7,5224.09 U3_Ch6.1@10100.7,5279.37
NetC19_Ch6_2: C19_Ch6.2 C21_Ch6.2 R29_Ch6.2 U3_Ch6.4 | length 217.6
  Top Layer w15: U3_Ch6.4@10250.7,5279.37 10250.7,5224.52 10237.83,5211.65 C19_Ch6.2@10202.26,5211.65 10201.7,5211.09 R29_Ch6.2@10201.7,5157.28 10248.77,5157.28 C21_Ch6.2@10253.91,5162.41
NetC19_Ch7_1: C19_Ch7.1 C22_Ch7.1 R28_Ch7.2 U3_Ch7.1 | length 214.4
  Top Layer w15: C22_Ch7.1@11658.91,5162.33 11664.04,5157.2 R28_Ch7.2@11709.7,5157.2 11709.7,5211.02 C19_Ch7.1@11709.14,5211.57 11675.14,5211.57 11662.7,5224.02 U3_Ch7.1@11662.7,5279.29
NetC19_Ch7_2: C19_Ch7.2 C21_Ch7.2 R29_Ch7.2 U3_Ch7.4 | length 217.6
  Top Layer w15: U3_Ch7.4@11812.7,5279.29 11812.7,5224.44 11799.83,5211.57 C19_Ch7.2@11764.26,5211.57 11763.7,5211.02 R29_Ch7.2@11763.7,5157.2 11810.77,5157.2 C21_Ch7.2@11815.91,5162.33
NetC19_Ch8_1: C19_Ch8.1 C22_Ch8.1 R28_Ch8.2 U3_Ch8.1 | length 214.4
  Top Layer w15: C22_Ch8.1@13220.91,5162.26 13226.04,5157.12 R28_Ch8.2@13271.7,5157.12 13271.7,5210.94 C19_Ch8.1@13271.14,5211.5 13237.14,5211.5 13224.7,5223.94 U3_Ch8.1@13224.7,5279.21
NetC19_Ch8_2: C19_Ch8.2 C21_Ch8.2 R29_Ch8.2 U3_Ch8.4 | length 217.6
  Top Layer w15: U3_Ch8.4@13374.7,5279.21 13374.7,5224.36 13361.83,5211.5 C19_Ch8.2@13326.26,5211.5 13325.7,5210.94 R29_Ch8.2@13325.7,5157.12 13372.77,5157.12 C21_Ch8.2@13377.91,5162.26
NetC25_Ch1_1: C25_Ch1.1 R33_Ch1.2 R34_Ch1.1 | length 132.1
  Top Layer w15: R33_Ch1.2@2057,5717.67 2057,5773.55 C25_Ch1.1@2050.5,5780.05 2057,5786.54 R34_Ch1.1@2057,5844.43
NetC25_Ch1_2: C25_Ch1.2 R37_Ch1.2 R38_Ch1.1 | length 133
  Top Layer w15: R37_Ch1.2@2106,5717.67 2106,5772.55 C25_Ch1.2@2113.5,5780.05 2106,5787.54 R38_Ch1.1@2106,5844.43
NetC25_Ch2_1: C25_Ch2.1 R33_Ch2.2 R34_Ch2.1 | length 132.1
  Top Layer w15: R33_Ch2.2@3619,5717.59 3619,5773.47 C25_Ch2.1@3612.5,5779.97 3619,5786.46 R34_Ch2.1@3619,5844.35
NetC25_Ch2_2: C25_Ch2.2 R37_Ch2.2 R38_Ch2.1 | length 133
  Top Layer w15: R37_Ch2.2@3668,5717.59 3668,5772.47 C25_Ch2.2@3675.5,5779.97 3668,5787.46 R38_Ch2.1@3668,5844.35
NetC25_Ch3_1: C25_Ch3.1 R33_Ch3.2 R34_Ch3.1 | length 132.1
  Top Layer w15: R33_Ch3.2@5181,5717.51 5181,5773.39 C25_Ch3.1@5174.5,5779.89 5181,5786.39 R34_Ch3.1@5181,5844.27
NetC25_Ch3_2: C25_Ch3.2 R37_Ch3.2 R38_Ch3.1 | length 133
  Top Layer w15: R37_Ch3.2@5230,5717.51 5230,5772.39 C25_Ch3.2@5237.5,5779.89 5230,5787.39 R38_Ch3.1@5230,5844.27
NetC25_Ch4_1: C25_Ch4.1 R33_Ch4.2 R34_Ch4.1 | length 132.1
  Top Layer w15: R33_Ch4.2@6743,5717.43 6743,5773.31 C25_Ch4.1@6736.5,5779.81 6743,5786.31 R34_Ch4.1@6743,5844.19
NetC25_Ch4_2: C25_Ch4.2 R37_Ch4.2 R38_Ch4.1 | length 133
  Top Layer w15: R37_Ch4.2@6792,5717.43 6792,5772.32 C25_Ch4.2@6799.5,5779.81 6792,5787.31 R38_Ch4.1@6792,5844.19
NetC25_Ch5_1: C25_Ch5.1 R33_Ch5.2 R34_Ch5.1 | length 132.1
  Top Layer w15: R33_Ch5.2@8698.7,5717.35 8698.7,5773.24 C25_Ch5.1@8692.2,5779.73 8698.7,5786.23 R34_Ch5.1@8698.7,5844.11
NetC25_Ch5_2: C25_Ch5.2 R37_Ch5.2 R38_Ch5.1 | length 133
  Top Layer w15: R37_Ch5.2@8747.7,5717.35 8747.7,5772.24 C25_Ch5.2@8755.2,5779.73 8747.7,5787.23 R38_Ch5.1@8747.7,5844.11
NetC25_Ch6_1: C25_Ch6.1 R33_Ch6.2 R34_Ch6.1 | length 132.1
  Top Layer w15: R33_Ch6.2@10260.7,5717.28 10260.7,5773.16 C25_Ch6.1@10254.2,5779.65 10260.7,5786.15 R34_Ch6.1@10260.7,5844.03
NetC25_Ch6_2: C25_Ch6.2 R37_Ch6.2 R38_Ch6.1 | length 133
  Top Layer w15: R37_Ch6.2@10309.7,5717.28 10309.7,5772.16 C25_Ch6.2@10317.2,5779.65 10309.7,5787.15 R38_Ch6.1@10309.7,5844.03
NetC25_Ch7_1: C25_Ch7.1 R33_Ch7.2 R34_Ch7.1 | length 132.1
  Top Layer w15: R33_Ch7.2@11822.7,5717.2 11822.7,5773.08 C25_Ch7.1@11816.2,5779.57 11822.7,5786.07 R34_Ch7.1@11822.7,5843.95
NetC25_Ch7_2: C25_Ch7.2 R37_Ch7.2 R38_Ch7.1 | length 133
  Top Layer w15: R37_Ch7.2@11871.7,5717.2 11871.7,5772.08 C25_Ch7.2@11879.2,5779.57 11871.7,5787.07 R38_Ch7.1@11871.7,5843.95
NetC25_Ch8_1: C25_Ch8.1 R33_Ch8.2 R34_Ch8.1 | length 132.1
  Top Layer w15: R33_Ch8.2@13384.7,5717.12 13384.7,5773 C25_Ch8.1@13378.2,5779.5 13384.7,5785.99 R34_Ch8.1@13384.7,5843.87
NetC25_Ch8_2: C25_Ch8.2 R37_Ch8.2 R38_Ch8.1 | length 133
  Top Layer w15: R37_Ch8.2@13433.7,5717.12 13433.7,5772 C25_Ch8.2@13441.2,5779.5 13433.7,5786.99 R38_Ch8.1@13433.7,5843.87
NetC26_Ch1_1: C26_Ch1.1 R34_Ch1.2 R35_Ch1.1 | length 130.1
  Top Layer w15: R34_Ch1.2@2057,5891.67 2057,5948.55 C26_Ch1.1@2050.5,5955.05 2057,5961.54 R35_Ch1.1@2057,6016.43
NetC26_Ch1_2: C26_Ch1.2 R38_Ch1.2 R39_Ch1.1 | length 131
  Top Layer w15: R38_Ch1.2@2106,5891.67 2106,5947.55 C26_Ch1.2@2113.5,5955.05 2106,5962.54 R39_Ch1.1@2106,6016.43
NetC26_Ch2_1: C26_Ch2.1 R34_Ch2.2 R35_Ch2.1 | length 130.1
  Top Layer w15: R34_Ch2.2@3619,5891.59 3619,5948.47 C26_Ch2.1@3612.5,5954.97 3619,5961.46 R35_Ch2.1@3619,6016.35
NetC26_Ch2_2: C26_Ch2.2 R38_Ch2.2 R39_Ch2.1 | length 131
  Top Layer w15: R38_Ch2.2@3668,5891.59 3668,5947.47 C26_Ch2.2@3675.5,5954.97 3668,5962.46 R39_Ch2.1@3668,6016.35
NetC26_Ch3_1: C26_Ch3.1 R34_Ch3.2 R35_Ch3.1 | length 130.1
  Top Layer w15: R34_Ch3.2@5181,5891.51 5181,5948.39 C26_Ch3.1@5174.5,5954.89 5181,5961.39 R35_Ch3.1@5181,6016.27
NetC26_Ch3_2: C26_Ch3.2 R38_Ch3.2 R39_Ch3.1 | length 131
  Top Layer w15: R38_Ch3.2@5230,5891.51 5230,5947.39 C26_Ch3.2@5237.5,5954.89 5230,5962.39 R39_Ch3.1@5230,6016.27
NetC26_Ch4_1: C26_Ch4.1 R34_Ch4.2 R35_Ch4.1 | length 130.1
  Top Layer w15: R34_Ch4.2@6743,5891.43 6743,5948.31 C26_Ch4.1@6736.5,5954.81 6743,5961.31 R35_Ch4.1@6743,6016.19
NetC26_Ch4_2: C26_Ch4.2 R38_Ch4.2 R39_Ch4.1 | length 131
  Top Layer w15: R38_Ch4.2@6792,5891.43 6792,5947.32 C26_Ch4.2@6799.5,5954.81 6792,5962.31 R39_Ch4.1@6792,6016.19
NetC26_Ch5_1: C26_Ch5.1 R34_Ch5.2 R35_Ch5.1 | length 130.1
  Top Layer w15: R34_Ch5.2@8698.7,5891.35 8698.7,5948.24 C26_Ch5.1@8692.2,5954.73 8698.7,5961.23 R35_Ch5.1@8698.7,6016.11
NetC26_Ch5_2: C26_Ch5.2 R38_Ch5.2 R39_Ch5.1 | length 131
  Top Layer w15: R38_Ch5.2@8747.7,5891.35 8747.7,5947.24 C26_Ch5.2@8755.2,5954.73 8747.7,5962.23 R39_Ch5.1@8747.7,6016.11
NetC26_Ch6_1: C26_Ch6.1 R34_Ch6.2 R35_Ch6.1 | length 130.1
  Top Layer w15: R34_Ch6.2@10260.7,5891.28 10260.7,5948.16 C26_Ch6.1@10254.2,5954.65 10260.7,5961.15 R35_Ch6.1@10260.7,6016.03
NetC26_Ch6_2: C26_Ch6.2 R38_Ch6.2 R39_Ch6.1 | length 131
  Top Layer w15: R38_Ch6.2@10309.7,5891.28 10309.7,5947.16 C26_Ch6.2@10317.2,5954.65 10309.7,5962.15 R39_Ch6.1@10309.7,6016.03
NetC26_Ch7_1: C26_Ch7.1 R34_Ch7.2 R35_Ch7.1 | length 130.1
  Top Layer w15: R34_Ch7.2@11822.7,5891.2 11822.7,5948.08 C26_Ch7.1@11816.2,5954.57 11822.7,5961.07 R35_Ch7.1@11822.7,6015.95
NetC26_Ch7_2: C26_Ch7.2 R38_Ch7.2 R39_Ch7.1 | length 131
  Top Layer w15: R38_Ch7.2@11871.7,5891.2 11871.7,5947.08 C26_Ch7.2@11879.2,5954.57 11871.7,5962.07 R39_Ch7.1@11871.7,6015.95
NetC26_Ch8_1: C26_Ch8.1 R34_Ch8.2 R35_Ch8.1 | length 130.1
  Top Layer w15: R34_Ch8.2@13384.7,5891.12 13384.7,5948 C26_Ch8.1@13378.2,5954.5 13384.7,5960.99 R35_Ch8.1@13384.7,6015.87
NetC26_Ch8_2: C26_Ch8.2 R38_Ch8.2 R39_Ch8.1 | length 131
  Top Layer w15: R38_Ch8.2@13433.7,5891.12 13433.7,5947 C26_Ch8.2@13441.2,5954.5 13433.7,5961.99 R39_Ch8.1@13433.7,6015.87
NetC27_Ch1_1: C27_Ch1.1 R35_Ch1.2 R36_Ch1.1 | length 2209.3
  Top Layer w10: C27_Ch1.1@2050.5,6125.05 2072,6146.54 2072,6203.7 3258.43,7390.13 3617.75,7390.13 R36_Ch1.1@3632.25,7404.63
  Top Layer w15: C27_Ch1.1@2050.5,6125.05 2057,6118.55 R35_Ch1.2@2057,6063.67
NetC27_Ch1_2: C27_Ch1.2 R39_Ch1.2 R40_Ch1.1 | length 2176.6
  Top Layer w10: C27_Ch1.2@2113.5,6125.05 2092,6146.54 2092,6195.42 3266.72,7370.13 3617.75,7370.13 R40_Ch1.1@3632.25,7355.63
  Top Layer w15: R39_Ch1.2@2106,6063.67 2106,6117.55 C27_Ch1.2@2113.5,6125.05
NetC27_Ch2_1: C27_Ch2.1 R35_Ch2.2 R36_Ch2.1 | length 701
  Top Layer w10: C27_Ch2.1@3612.5,6124.97 3634,6146.46 3634,6207.2 3675.5,6248.7 3793,6248.7 3976.25,6431.95 3976.25,6521.93 R36_Ch2.1@3961.75,6536.43
  Top Layer w15: C27_Ch2.1@3612.5,6124.97 3619,6118.47 R35_Ch2.2@3619,6063.59
NetC27_Ch2_2: C27_Ch2.2 R39_Ch2.2 R40_Ch2.1 | length 701.4
  Top Layer w10: C27_Ch2.2@3675.5,6124.97 3654,6146.46 3654,6198.91 3683.79,6228.7 3801.28,6228.7 3996.25,6423.67 3996.25,6521.93 R40_Ch2.1@4010.75,6536.43
  Top Layer w15: R39_Ch2.2@3668,6063.59 3668,6117.47 C27_Ch2.2@3675.5,6124.97
NetC27_Ch3_1: C27_Ch3.1 R35_Ch3.2 R36_Ch3.1 | length 1090.9
  Top Layer w10: R36_Ch3.1@4481.61,6536.43 4496.11,6521.93 4496.11,6360.3 4614.72,6241.7 5144.72,6241.7 5196,6190.42 5196,6146.39 C27_Ch3.1@5174.5,6124.89
  Top Layer w15: C27_Ch3.1@5174.5,6124.89 5181,6118.39 R35_Ch3.2@5181,6063.51
NetC27_Ch3_2: C27_Ch3.2 R39_Ch3.2 R40_Ch3.1 | length 1091.3
  Top Layer w10: R40_Ch3.1@4530.61,6536.43 4516.11,6521.93 4516.11,6368.59 4623,6261.7 5153,6261.7 5216,6198.7 5216,6146.39 C27_Ch3.2@5237.5,6124.89
  Top Layer w15: R39_Ch3.2@5230,6063.51 5230,6117.39 C27_Ch3.2@5237.5,6124.89
NetC27_Ch4_1: C27_Ch4.1 R35_Ch4.2 R36_Ch4.1 | length 2174.7
  Top Layer w10: R36_Ch4.1@5121.04,7085.03 5135.54,7099.53 5184.89,7099.53 5974.72,6309.7 6667,6309.7 6758,6218.7 6758,6146.31 C27_Ch4.1@6736.5,6124.81
  Top Layer w15: C27_Ch4.1@6736.5,6124.81 6743,6118.31 R35_Ch4.2@6743,6063.43
NetC27_Ch4_2: C27_Ch4.2 R39_Ch4.2 R40_Ch4.1 | length 2208.2
  Top Layer w10: R40_Ch4.1@5121.04,7134.03 5135.54,7119.53 5193.17,7119.53 5983,6329.7 6675.28,6329.7 6778,6226.98 6778,6146.31 C27_Ch4.2@6799.5,6124.81
  Top Layer w15: R39_Ch4.2@6792,6063.43 6792,6117.32 C27_Ch4.2@6799.5,6124.81
NetC27_Ch5_1: C27_Ch5.1 R35_Ch5.2 R36_Ch5.1 | length 2209.3
  Top Layer w10: C27_Ch5.1@8692.2,6124.73 8713.7,6146.23 8713.7,6203.39 9900.13,7389.82 10259.45,7389.82 R36_Ch5.1@10273.95,7404.32
  Top Layer w15: C27_Ch5.1@8692.2,6124.73 8698.7,6118.24 R35_Ch5.2@8698.7,6063.35
NetC27_Ch5_2: C27_Ch5.2 R39_Ch5.2 R40_Ch5.1 | length 2187.2
  Top Layer w10: C27_Ch5.2@8755.2,6124.73 8733.7,6146.23 8733.7,6195.1 9908.42,7369.82 10259.45,7369.82 R40_Ch5.1@10273.95,7355.32
  Top Layer w15: R39_Ch5.2@8747.7,6063.35 C27_Ch5.2@8747.7,6117.24 ; C27_Ch5.2@8747.7,6117.24 C27_Ch5.2@8755.2,6124.73 C27_Ch5.2@8747.7,6117.24
NetC27_Ch6_1: C27_Ch6.1 R35_Ch6.2 R36_Ch6.1 | length 701
  Top Layer w10: C27_Ch6.1@10254.2,6124.65 10275.7,6146.15 10275.7,6206.88 10317.2,6248.39 10434.7,6248.39 10617.95,6431.64 10617.95,6521.61 R36_Ch6.1@10603.45,6536.11
  Top Layer w15: C27_Ch6.1@10254.2,6124.65 10260.7,6118.16 R35_Ch6.2@10260.7,6063.28
NetC27_Ch6_2: C27_Ch6.2 R39_Ch6.2 R40_Ch6.1 | length 701.4
  Top Layer w10: C27_Ch6.2@10317.2,6124.65 10295.7,6146.15 10295.7,6198.6 10325.49,6228.39 10442.99,6228.39 10637.95,6423.35 10637.95,6521.61 R40_Ch6.1@10652.45,6536.11
  Top Layer w15: R39_Ch6.2@10309.7,6063.28 10309.7,6117.16 C27_Ch6.2@10317.2,6124.65
NetC27_Ch7_1: C27_Ch7.1 R35_Ch7.2 R36_Ch7.1 | length 1090.9
  Top Layer w10: R36_Ch7.1@11123.31,6536.11 11137.81,6521.61 11137.81,6359.99 11256.42,6241.39 11786.42,6241.39 11837.7,6190.1 11837.7,6146.07 C27_Ch7.1@11816.2,6124.57
  Top Layer w15: C27_Ch7.1@11816.2,6124.57 11822.7,6118.08 R35_Ch7.2@11822.7,6063.2
NetC27_Ch7_2: C27_Ch7.2 R39_Ch7.2 R40_Ch7.1 | length 1091.3
  Top Layer w10: R40_Ch7.1@11172.31,6536.11 11157.81,6521.61 11157.81,6368.27 11264.7,6261.39 11794.7,6261.39 11857.7,6198.39 11857.7,6146.07 C27_Ch7.2@11879.2,6124.57
  Top Layer w15: R39_Ch7.2@11871.7,6063.2 11871.7,6117.08 C27_Ch7.2@11879.2,6124.57
NetC27_Ch8_1: C27_Ch8.1 R35_Ch8.2 R36_Ch8.1 | length 2174.7
  Top Layer w10: R36_Ch8.1@11762.74,7084.71 11777.24,7099.21 11826.59,7099.21 12616.42,6309.39 13308.7,6309.39 13399.7,6218.39 13399.7,6145.99 C27_Ch8.1@13378.2,6124.5
  Top Layer w15: C27_Ch8.1@13378.2,6124.5 13384.7,6118 R35_Ch8.2@13384.7,6063.12
NetC27_Ch8_2: C27_Ch8.2 R39_Ch8.2 R40_Ch8.1 | length 2208.2
  Top Layer w10: R40_Ch8.1@11762.74,7133.71 11777.24,7119.21 11834.87,7119.21 12624.7,6329.39 13316.99,6329.39 13419.7,6226.67 13419.7,6145.99 C27_Ch8.2@13441.2,6124.5
  Top Layer w15: R39_Ch8.2@13433.7,6063.12 13433.7,6117 C27_Ch8.2@13441.2,6124.5
NetC32_Ch1_1: C32_Ch1.1 C36_Ch1.1 R45_Ch1.2 U4_Ch1.4 | length 180.7
  Bottom Layer w15: U4_Ch1.4@2377.59,5512.76 2377.59,5462.02 C32_Ch1.1@2390.56,5449.05 2390.56,5388.23 R45_Ch1.2@2390,5387.67 2439.94,5387.67 C36_Ch1.1@2440,5387.61
NetC32_Ch1_2: C32_Ch1.2 C35_Ch1.2 R47_Ch1.2 U4_Ch1.5 | length 184.6
  Bottom Layer w15: C35_Ch1.2@2291,5388.61 2291.94,5387.67 R47_Ch1.2@2341,5387.67 2341,5443.49 C32_Ch1.2@2335.44,5449.05 2352,5465.61 U4_Ch1.5@2352,5512.76
NetC32_Ch2_1: C32_Ch2.1 C36_Ch2.1 R45_Ch2.2 U4_Ch2.4 | length 180.7
  Bottom Layer w15: U4_Ch2.4@3939.59,5512.68 3939.59,5461.94 C32_Ch2.1@3952.56,5448.97 3952.56,5388.15 R45_Ch2.2@3952,5387.59 4001.94,5387.59 C36_Ch2.1@4002,5387.53
NetC32_Ch2_2: C32_Ch2.2 C35_Ch2.2 R47_Ch2.2 U4_Ch2.5 | length 184.6
  Bottom Layer w15: C35_Ch2.2@3853,5388.53 3853.94,5387.59 R47_Ch2.2@3903,5387.59 3903,5443.41 C32_Ch2.2@3897.44,5448.97 3914,5465.53 U4_Ch2.5@3914,5512.68
NetC32_Ch3_1: C32_Ch3.1 C36_Ch3.1 R45_Ch3.2 U4_Ch3.4 | length 180.7
  Bottom Layer w15: U4_Ch3.4@5501.59,5512.6 5501.59,5461.86 C32_Ch3.1@5514.56,5448.89 5514.56,5388.07 R45_Ch3.2@5514,5387.51 5563.94,5387.51 C36_Ch3.1@5564,5387.45
NetC32_Ch3_2: C32_Ch3.2 C35_Ch3.2 R47_Ch3.2 U4_Ch3.5 | length 184.6
  Bottom Layer w15: C35_Ch3.2@5415,5388.45 5415.94,5387.51 R47_Ch3.2@5465,5387.51 5465,5443.33 C32_Ch3.2@5459.44,5448.89 5476,5465.45 U4_Ch3.5@5476,5512.6
NetC32_Ch4_1: C32_Ch4.1 C36_Ch4.1 R45_Ch4.2 U4_Ch4.4 | length 180.7
  Bottom Layer w15: U4_Ch4.4@7063.59,5512.52 7063.59,5461.78 C32_Ch4.1@7076.56,5448.81 7076.56,5387.99 R45_Ch4.2@7076,5387.43 7125.94,5387.43 C36_Ch4.1@7126,5387.37
NetC32_Ch4_2: C32_Ch4.2 C35_Ch4.2 R47_Ch4.2 U4_Ch4.5 | length 184.6
  Bottom Layer w15: C35_Ch4.2@6977,5388.37 6977.94,5387.43 R47_Ch4.2@7027,5387.43 7027,5443.25 C32_Ch4.2@7021.44,5448.81 7038,5465.37 U4_Ch4.5@7038,5512.52
NetC32_Ch5_1: C32_Ch5.1 C36_Ch5.1 R45_Ch5.2 U4_Ch5.4 | length 180.7
  Bottom Layer w15: U4_Ch5.4@9019.29,5512.44 9019.29,5461.7 C32_Ch5.1@9032.26,5448.73 9032.26,5387.91 R45_Ch5.2@9031.7,5387.35 9081.64,5387.35 C36_Ch5.1@9081.7,5387.29
NetC32_Ch5_2: C32_Ch5.2 C35_Ch5.2 R47_Ch5.2 U4_Ch5.5 | length 184.6
  Bottom Layer w15: C35_Ch5.2@8932.7,5388.29 8933.64,5387.35 R47_Ch5.2@8982.7,5387.35 8982.7,5443.17 C32_Ch5.2@8977.14,5448.73 8993.7,5465.29 U4_Ch5.5@8993.7,5512.44
NetC32_Ch6_1: C32_Ch6.1 C36_Ch6.1 R45_Ch6.2 U4_Ch6.4 | length 180.7
  Bottom Layer w15: U4_Ch6.4@10581.29,5512.36 10581.29,5461.62 C32_Ch6.1@10594.26,5448.65 10594.26,5387.83 R45_Ch6.2@10593.7,5387.28 10643.64,5387.28 C36_Ch6.1@10643.7,5387.21
NetC32_Ch6_2: C32_Ch6.2 C35_Ch6.2 R47_Ch6.2 U4_Ch6.5 | length 184.6
  Bottom Layer w15: C35_Ch6.2@10494.7,5388.21 10495.64,5387.28 R47_Ch6.2@10544.7,5387.28 10544.7,5443.09 C32_Ch6.2@10539.14,5448.65 10555.7,5465.21 U4_Ch6.5@10555.7,5512.36
NetC32_Ch7_1: C32_Ch7.1 C36_Ch7.1 R45_Ch7.2 U4_Ch7.4 | length 180.7
  Bottom Layer w15: U4_Ch7.4@12143.29,5512.28 12143.29,5461.54 C32_Ch7.1@12156.26,5448.57 12156.26,5387.76 R45_Ch7.2@12155.7,5387.2 12205.64,5387.2 C36_Ch7.1@12205.7,5387.13
NetC32_Ch7_2: C32_Ch7.2 C35_Ch7.2 R47_Ch7.2 U4_Ch7.5 | length 184.6
  Bottom Layer w15: C35_Ch7.2@12056.7,5388.13 12057.64,5387.2 R47_Ch7.2@12106.7,5387.2 12106.7,5443.02 C32_Ch7.2@12101.14,5448.57 12117.7,5465.13 U4_Ch7.5@12117.7,5512.28
NetC32_Ch8_1: C32_Ch8.1 C36_Ch8.1 R45_Ch8.2 U4_Ch8.4 | length 180.7
  Bottom Layer w15: U4_Ch8.4@13705.29,5512.2 13705.29,5461.46 C32_Ch8.1@13718.26,5448.5 13718.26,5387.68 R45_Ch8.2@13717.7,5387.12 13767.64,5387.12 C36_Ch8.1@13767.7,5387.06
NetC32_Ch8_2: C32_Ch8.2 C35_Ch8.2 R47_Ch8.2 U4_Ch8.5 | length 184.6
  Bottom Layer w15: C35_Ch8.2@13618.7,5388.06 13619.64,5387.12 R47_Ch8.2@13668.7,5387.12 13668.7,5442.94 C32_Ch8.2@13663.14,5448.5 13679.7,5465.06 U4_Ch8.5@13679.7,5512.2
NetC37_Ch1_1: C37_Ch1.1 R51_Ch1.2 U6_Ch1.5 | length 125.9
  Bottom Layer w15: R51_Ch1.2@1995,6000.29 C37_Ch1.1@1995,6063.05 2057.72,6063.05 U6_Ch1.5@2058,6063.33
NetC37_Ch2_1: C37_Ch2.1 R51_Ch2.2 U6_Ch2.5 | length 125.9
  Bottom Layer w15: R51_Ch2.2@3557,6000.21 C37_Ch2.1@3557,6062.97 3619.72,6062.97 U6_Ch2.5@3620,6063.25
NetC37_Ch3_1: C37_Ch3.1 R51_Ch3.2 U6_Ch3.5 | length 125.9
  Bottom Layer w15: R51_Ch3.2@5119,6000.13 C37_Ch3.1@5119,6062.89 5181.72,6062.89 U6_Ch3.5@5182,6063.17
NetC37_Ch4_1: C37_Ch4.1 R51_Ch4.2 U6_Ch4.5 | length 125.9
  Bottom Layer w15: R51_Ch4.2@6681,6000.06 C37_Ch4.1@6681,6062.81 6743.72,6062.81 U6_Ch4.5@6744,6063.09
NetC37_Ch5_1: C37_Ch5.1 R51_Ch5.2 U6_Ch5.5 | length 125.9
  Bottom Layer w15: R51_Ch5.2@8636.7,5999.98 C37_Ch5.1@8636.7,6062.73 8699.42,6062.73 U6_Ch5.5@8699.7,6063.02
NetC37_Ch6_1: C37_Ch6.1 R51_Ch6.2 U6_Ch6.5 | length 125.9
  Bottom Layer w15: R51_Ch6.2@10198.7,5999.9 C37_Ch6.1@10198.7,6062.65 10261.42,6062.65 U6_Ch6.5@10261.7,6062.94
NetC37_Ch7_1: C37_Ch7.1 R51_Ch7.2 U6_Ch7.5 | length 125.9
  Bottom Layer w15: R51_Ch7.2@11760.7,5999.82 C37_Ch7.1@11760.7,6062.57 11823.42,6062.57 U6_Ch7.5@11823.7,6062.86
NetC37_Ch8_1: C37_Ch8.1 R51_Ch8.2 U6_Ch8.5 | length 125.9
  Bottom Layer w15: R51_Ch8.2@13322.7,5999.74 C37_Ch8.1@13322.7,6062.5 13385.42,6062.5 U6_Ch8.5@13385.7,6062.78
NetC38_Ch1_1: C38_Ch1.1 R53_Ch1.2 U6_Ch1.3 | length 142.9
  Bottom Layer w15: U6_Ch1.3@2108,5848.76 2108.38,5848.39 C38_Ch1.1@2108.38,5756.05 R53_Ch1.2@2108.38,5706.05
NetC38_Ch2_1: C38_Ch2.1 R53_Ch2.2 U6_Ch2.3 | length 142.9
  Bottom Layer w15: U6_Ch2.3@3670,5848.68 3670.38,5848.31 C38_Ch2.1@3670.38,5755.97 R53_Ch2.2@3670.38,5705.97
NetC38_Ch3_1: C38_Ch3.1 R53_Ch3.2 U6_Ch3.3 | length 142.9
  Bottom Layer w15: U6_Ch3.3@5232,5848.61 5232.38,5848.23 C38_Ch3.1@5232.38,5755.89 R53_Ch3.2@5232.38,5705.89
NetC38_Ch4_1: C38_Ch4.1 R53_Ch4.2 U6_Ch4.3 | length 142.9
  Bottom Layer w15: U6_Ch4.3@6794,5848.53 6794.38,5848.15 C38_Ch4.1@6794.38,5755.81 R53_Ch4.2@6794.38,5705.81
NetC38_Ch5_1: C38_Ch5.1 R53_Ch5.2 U6_Ch5.3 | length 142.9
  Bottom Layer w15: U6_Ch5.3@8749.7,5848.45 8750.08,5848.07 C38_Ch5.1@8750.08,5755.73 R53_Ch5.2@8750.08,5705.73
NetC38_Ch6_1: C38_Ch6.1 R53_Ch6.2 U6_Ch6.3 | length 142.9
  Bottom Layer w15: U6_Ch6.3@10311.7,5848.37 10312.08,5847.99 C38_Ch6.1@10312.08,5755.65 R53_Ch6.2@10312.08,5705.65
NetC38_Ch7_1: C38_Ch7.1 R53_Ch7.2 U6_Ch7.3 | length 142.9
  Bottom Layer w15: U6_Ch7.3@11873.7,5848.29 11874.08,5847.91 C38_Ch7.1@11874.08,5755.57 R53_Ch7.2@11874.08,5705.57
